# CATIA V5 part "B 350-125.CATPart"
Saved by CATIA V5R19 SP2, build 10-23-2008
Part number: B 350-125
Bounding box of the stored display mesh (mm): x -15.868 to 15.868, y -15.868 to 15.868, z 0 to 300
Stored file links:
  C:\Users\Bora\Desktop\3D Katı model\B serisi\B 350\B 350-125.CATPart
  C:\Program Files\Dassault Systemes\B19\intel_a\reffiles\standard\MetricThickPitch.txt
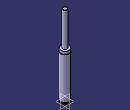
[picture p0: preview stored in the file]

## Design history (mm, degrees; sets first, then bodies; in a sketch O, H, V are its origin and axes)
Body1 (main body)
  Sketch1 on yz-plane, origin (0, 0, 0), H (0, 1, 0), V (0, 0, 1)
    point P1 (16, 163.5)
    point P4 (16, 161.5)
    point P7 (16, 163.5)
    point P8 (16, 161.5)
    point P9 (8, 299)
    point P11 (8, 299)
    line L1 (16, 163.5) -> (16, 173)
    line L2 (16, 7.5) -> (16, 161.5)
    line L3 (13.5, 7.5) -> (13.5, 4)
    arc A1 centre (16, 162.5) radius 1 from (16, 163.5) to (16, 161.5) ccw
    arc A2 centre (7, 299) radius 1 from (8, 299) to (7, 300) ccw
    line L4 (8, 299) -> (8, 173)
    line L5 (16, 0) -> (16, 4)
    line L6 (7, 300) -> (0, 300)
    point P15 (0, 300)
    line L7 (8, 173) -> (16, 173)
    line L8 (0, 0) -> (16, 0)
    line L9 (13.5, 7.5) -> (16, 7.5)
    line L10 (13.5, 4) -> (16, 4)
    coincidence: P15 V, P1 P7, P4 P8, P9 P11
    tangency: L6 A2
    horizontal: L7 H, L8 H, L9 H, L10 H
  Shaft1: profile Sketch1, axis Sketch1.V, angle 360
  Sketch2 on face of Shaft1 from Sketch1.L8, origin (0, 0, 0), H (1, 0, 0), V (0, -1, 0)
    point P1 (0, 0)
  Hole1: placed by Sketch2, at (0, 0, 0) direction (0, 0, 1), diameter 6.647, depth 7, threaded "M8", thread diameter 8, thread depth 7, pitch 1.25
